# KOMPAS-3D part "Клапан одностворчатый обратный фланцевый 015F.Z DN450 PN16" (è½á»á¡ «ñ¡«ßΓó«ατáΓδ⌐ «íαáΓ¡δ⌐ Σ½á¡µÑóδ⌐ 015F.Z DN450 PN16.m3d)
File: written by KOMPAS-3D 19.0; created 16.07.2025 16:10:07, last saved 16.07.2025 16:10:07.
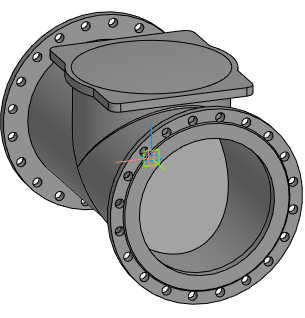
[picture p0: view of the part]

Document properties: Полное имя файла: E:\Dendor Работа Сачек\3D для проектировщиков\5.4 Тип 015F.Z. Клапан одностворчатый обратный фланцевый\stp_Клапан одностворчатый обратный фланцевый 015F.Z PN10_16\Клапан одностворчатый обратный фланцевый 015F.Z DN450 PN16.m3d

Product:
- Part/product: Клапан одностворчатый обратный фланцевый 015F.Z DN450 PN16

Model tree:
1. Операция без истории:1  (labels: Клапан одностворчатый обратный фланцевый 015F.Z DN450 PN16)
2. Операция без истории:2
